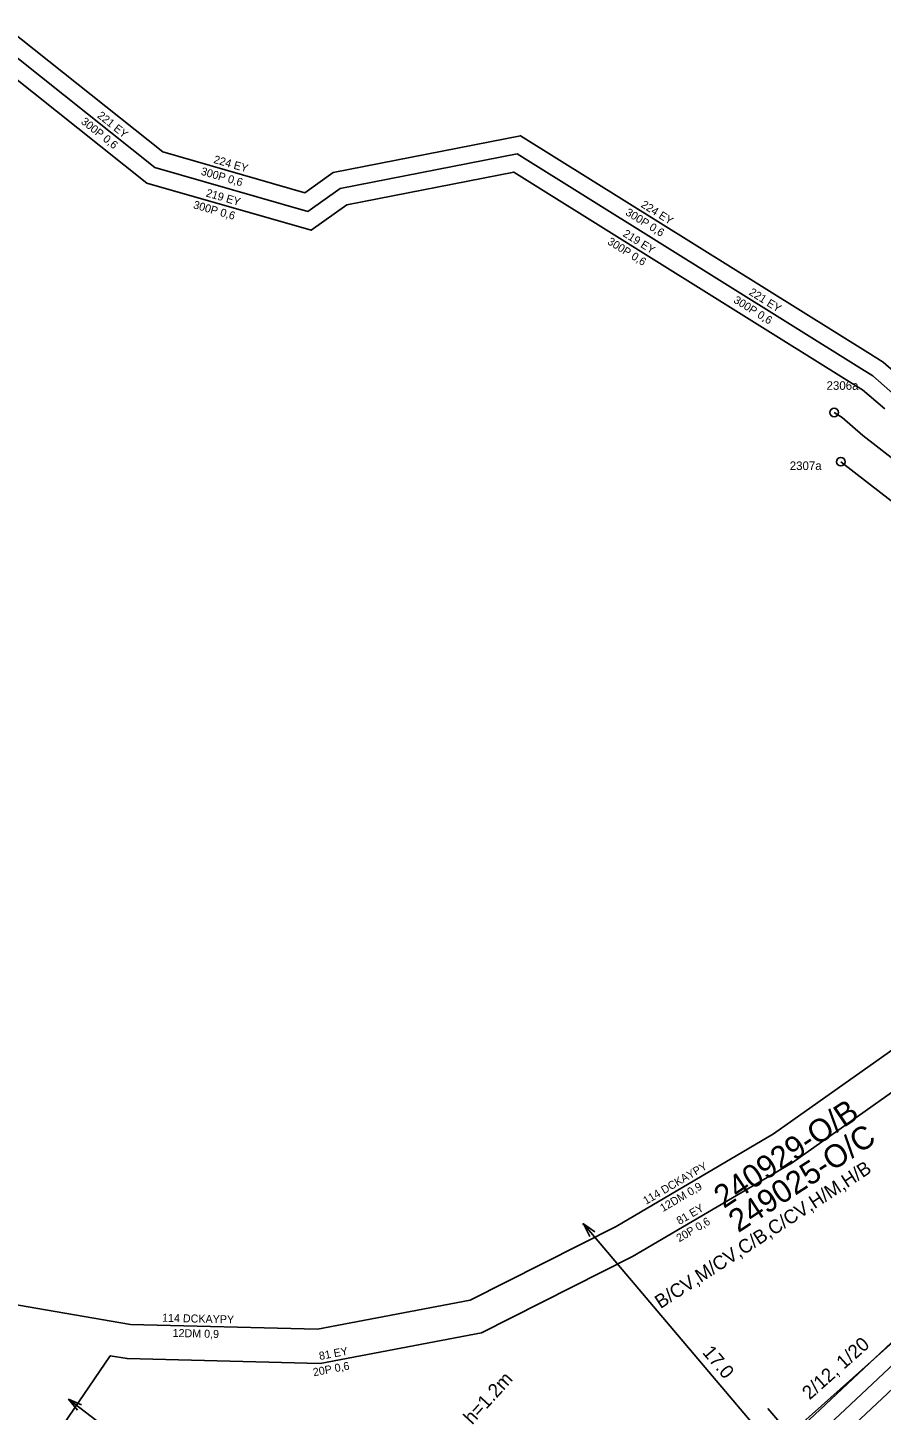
# Model space of a CAD drawing. Extents: x -756413 to -755757, y -1139003 to -1138237.
# Drawn here: x -756305.6 to -756268.2, y -1138347.7 to -1138287.2 of the extents above; entities that cross this region are included whole.
import ezdxf

# ---------------------------------------------------------------- set-up
doc = ezdxf.new("R2010")
doc.units = 0
for name, color, linetype in [('f003_opt_sit_texty', 7, 'Continuous'), ('f004_popis_kab_zil', 7, 'Continuous'), ('f006_osa_trasy', 7, 'Continuous'), ('f006_stp_koty', 7, 'Continuous'), ('f006_stp_linie', 7, 'Continuous'), ('f007_rezkynet_texty', 7, 'Continuous'), ('f307_kabel_metal', 7, 'Continuous'), ('f307_kabel_metal_ann', 7, 'Continuous'), ('f307_spojka_metal', 7, 'Continuous'), ('f307_spojka_metal_ann', 7, 'Continuous')]:
    doc.layers.add(name, color=color, linetype=linetype)

msp = doc.modelspace()

# ---------------------------------------------------------------- linework, layer by layer
at = {"layer": 'f006_osa_trasy'}
msp.add_lwpolyline([(-756263.68, -1138341.08), (-756271.81, -1138348.33), (-756280.66, -1138356.27), (-756284.45, -1138360.01), (-756285.07, -1138361.43), (-756284.11, -1138363.72), (-756283.96, -1138363.95)], dxfattribs=at)
at = {"layer": 'f006_stp_koty'}
for p, q in [((-756281.269, -1138339.521), (-756281.315, -1138339.56)), ((-756270.31, -1138352.47), (-756281.269, -1138339.521)), ((-756282.76, -1138363.17), (-756303.769, -1138347.2)), ((-756268.593, -1138352.972), (-756273.21, -1138347.6))]:
    msp.add_line(p, q, dxfattribs=at)
for points in [[(-756280.995, -1138340.075), (-756281.269, -1138339.521), (-756280.766, -1138339.882)], [(-756303.382, -1138347.682), (-756303.769, -1138347.2), (-756303.2, -1138347.443)]]:
    msp.add_lwpolyline(points, dxfattribs=at)
at = {"layer": 'f006_stp_linie'}
msp.add_lwpolyline([(-756263.68, -1138341.08), (-756271.81, -1138348.33), (-756280.66, -1138356.27), (-756284.45, -1138360.01), (-756285.07, -1138361.43), (-756284.11, -1138363.72), (-756283.96, -1138363.95), (-756281.46, -1138366.1), (-756278.21, -1138368.9), (-756278.22, -1138369.94), (-756276.79, -1138371.01), (-756276.1, -1138370.67), (-756273.86, -1138372.46), (-756269.86, -1138375.63), (-756266.87, -1138377.6), (-756265.9, -1138378.21), (-756263.89, -1138379.52), (-756259.67, -1138381.76), (-756256.89, -1138383.07), (-756253.65, -1138384.58), (-756249.42, -1138386.4), (-756248.03, -1138387), (-756242.76, -1138388.83), (-756238.48, -1138390.05)], dxfattribs=at)
at = {"layer": 'f307_kabel_metal'}
for points in [[(-756306.485, -1138287.215), (-756299.649, -1138292.651), (-756293.451, -1138294.434), (-756292.208, -1138293.55), (-756284.024, -1138291.942), (-756268.721, -1138301.5), (-756268.17, -1138301.844), (-756267.146, -1138302.732), (-756266.635, -1138303.13), (-756265.943, -1138303.667), (-756265.338, -1138304.142), (-756262.609, -1138306.261), (-756258.674, -1138313.461), (-756258.2, -1138314.363), (-756257.724, -1138315.263), (-756255.834, -1138321.418), (-756252.314, -1138325.16), (-756248.718, -1138323.124), (-756248.03, -1138322.735), (-756238.36, -1138317.525), (-756232.54, -1138311.52), (-756229.485, -1138308.375), (-756222.9, -1138304.16), (-756217, -1138310.915)], [(-756306.909, -1138287.836), (-756299.999, -1138293.331), (-756293.311, -1138295.255), (-756291.905, -1138294.255), (-756284.17, -1138292.735), (-756269.118, -1138302.136), (-756268.617, -1138302.449), (-756267.622, -1138303.312)], [(-756307.333, -1138288.457), (-756300.349, -1138294.011), (-756293.171, -1138296.076), (-756291.602, -1138294.96), (-756284.316, -1138293.528), (-756269.515, -1138302.772), (-756269.064, -1138303.054), (-756268.098, -1138303.892)], [(-756270.31, -1138304.044), (-756269.958, -1138304.264), (-756269.051, -1138305.051), (-756268.476, -1138305.498), (-756266.3, -1138307.19), (-756265.977, -1138306.494), (-756264.358, -1138307.752), (-756260.657, -1138314.525), (-756260.189, -1138315.413), (-756259.812, -1138316.127), (-756257.832, -1138322.579), (-756253.565, -1138327.113), (-756253.442, -1138327.243), (-756252.94, -1138327.745), (-756251.744, -1138327.422), (-756247.611, -1138325.083), (-756246.944, -1138324.706), (-756236.986, -1138319.34), (-756230.926, -1138313.086), (-756228.054, -1138310.13), (-756223.32, -1138307.1), (-756218.734, -1138312.352)], [(-756270.019, -1138306.197), (-756266.653, -1138308.817), (-756266.11, -1138309.24), (-756262.64, -1138315.59), (-756261.9, -1138316.99), (-756259.83, -1138323.74), (-756255.203, -1138328.655), (-756254.69, -1138329.2), (-756254.31, -1138329.67), (-756251.17, -1138328.82), (-756246.873, -1138326.389), (-756246.22, -1138326.02), (-756236.07, -1138320.55), (-756229.85, -1138314.13), (-756227.1, -1138311.3), (-756223.6, -1138309.06), (-756219.89, -1138313.31), (-756204.84, -1138332.43), (-756204.754, -1138332.538), (-756193.708, -1138346.394), (-756193.24, -1138346.98), (-756191.54, -1138349.16)], [(-756262.57, -1138317.363), (-756260.496, -1138324.127), (-756259.505, -1138325.18), (-756259.777, -1138325.43), (-756263.526, -1138328.915), (-756272.962, -1138335.593), (-756279.837, -1138339.642), (-756286.212, -1138342.863), (-756292.891, -1138344.13), (-756301.068, -1138343.923), (-756309.263, -1138342.52), (-756313.137, -1138339.946), (-756313.333, -1138340.073), (-756320.121, -1138347.951), (-756315.62, -1138351.591), (-756312.901, -1138354.115), (-756327.623, -1138366.698), (-756326.363, -1138368.116), (-756330.364, -1138371.464)], [(-756322.516, -1138359.073), (-756317.669, -1138363.776), (-756309.965, -1138357.043), (-756301.946, -1138345.295), (-756301.214, -1138345.42), (-756292.769, -1138345.634), (-756285.724, -1138344.297), (-756279.117, -1138340.959), (-756272.147, -1138336.854), (-756262.578, -1138330.082), (-756258.759, -1138326.532), (-756258.49, -1138326.284), (-756255.749, -1138329.169), (-756255.255, -1138329.693), (-756254.586, -1138330.522), (-756254.548, -1138330.753)], [(-756286.172, -1138361.983), (-756263.763, -1138340.926), (-756263.849, -1138340.814), (-756264.29, -1138340.12), (-756263.91, -1138338.97), (-756261.64, -1138336.8), (-756260.57, -1138336.81), (-756258.89, -1138336.13), (-756255.88, -1138335.14), (-756253.24, -1138333.92), (-756249.02, -1138331.33), (-756246.54, -1138329.07), (-756243.52, -1138326.47), (-756242.33, -1138326.52), (-756241, -1138327.21), (-756239.31, -1138329.02)], [(-756263.958, -1138368.536), (-756265.594, -1138368.168), (-756265.806, -1138368.427), (-756265.93, -1138368.578), (-756270.638, -1138374.339), (-756274.074, -1138371.597), (-756274.452, -1138371.278), (-756277.063, -1138368.941), (-756277.165, -1138368.852), (-756278.739, -1138367.609), (-756285.061, -1138361.969), (-756263.157, -1138341.386), (-756259.815, -1138345.149), (-756259.474, -1138344.879)], [(-756263.958, -1138368.536), (-756266.175, -1138367.693), (-756266.325, -1138367.877), (-756266.386, -1138367.951), (-756266.51, -1138368.103), (-756270.75, -1138373.29), (-756273.598, -1138371.017), (-756273.96, -1138370.712), (-756276.566, -1138368.379), (-756276.686, -1138368.275), (-756278.257, -1138367.034), (-756283.95, -1138361.955), (-756263.206, -1138342.461), (-756260.319, -1138345.711), (-756261.071, -1138346.345)]]:
    msp.add_lwpolyline(points, dxfattribs=at)
at = {"layer": 'f307_spojka_metal'}
for centre in [(-756270.31, -1138304.044), (-756270.019, -1138306.197)]:
    msp.add_circle(centre, 0.188, dxfattribs=at)

# ---------------------------------------------------------------- texts
at = {"layer": 'f003_opt_sit_texty'}
for s, height, rotation, p in [('240929-O/B', 1, 34.03, (-756275.13, -1138338.88)), ('249025-O/C', 1, 33.27, (-756274.5, -1138339.94)), ('B/CV,M/CV,C/B,C/CV,H/M,H/B', 0.6, 32.98, (-756277.9, -1138343.26))]:
    msp.add_text(s, height=height, rotation=rotation, dxfattribs=at).set_placement(p)
at = {"layer": 'f004_popis_kab_zil'}
msp.add_text('2/12, 1/20', height=0.6, rotation=41.73, dxfattribs=at).set_placement((-756271.38, -1138347.25))
at = {"layer": 'f006_stp_koty'}
msp.add_text('17.0', height=0.6, rotation=310.25, dxfattribs=at).set_placement((-756276.098, -1138345.166))
at = {"layer": 'f007_rezkynet_texty'}
msp.add_text('h=1.2m', height=0.6, rotation=47.67, dxfattribs=at).set_placement((-756286.13, -1138348.34))
at = {"layer": 'f307_kabel_metal_ann'}
for s, rotation, p in [('221 EY', 321.51, (-756302.546, -1138291.114)), (' 300P 0,6', 321.51, (-756303.359, -1138291.298)), (' 300P 0,6', 343.95, (-756298.14, -1138293.606)), ('224 EY', 343.95, (-756297.458, -1138293.125)), ('219 EY', 343.95, (-756297.791, -1138294.59)), (' 300P 0,6', 343.95, (-756298.473, -1138295.071)), (' 300P 0,6', 328.01, (-756279.571, -1138295.312)), ('224 EY', 328.01, (-756278.784, -1138295.038)), ('219 EY', 328.01, (-756279.574, -1138296.313)), (' 300P 0,6', 328.01, (-756280.361, -1138296.587)), ('221 EY', 328.01, (-756274.063, -1138298.871)), (' 300P 0,6', 328.01, (-756274.85, -1138299.145)), ('114 DCKAYPY', 30.5, (-756278.532, -1138338.699)), (' 12DM 0,9', 30.5, (-756277.904, -1138339.084)), ('81 EY', 30.5, (-756277.07, -1138339.58)), (' 20P 0,6', 30.5, (-756277.19, -1138340.405)), ('114 DCKAYPY', 358.55, (-756299.686, -1138343.808)), (' 12DM 0,9', 358.55, (-756299.357, -1138344.467)), ('81 EY', 10.75, (-756292.79, -1138345.485)), (' 20P 0,6', 10.75, (-756293.182, -1138346.221))]:
    msp.add_text(s, height=0.35, rotation=rotation, dxfattribs=at).set_placement(p)
at = {"layer": 'f307_spojka_metal_ann'}
for s, p in [('2306a', (-756270.641, -1138303.054)), ('2307a', (-756272.25, -1138306.56))]:
    msp.add_text(s, height=0.375, dxfattribs=at).set_placement(p)

doc.saveas('drawing.dxf')
